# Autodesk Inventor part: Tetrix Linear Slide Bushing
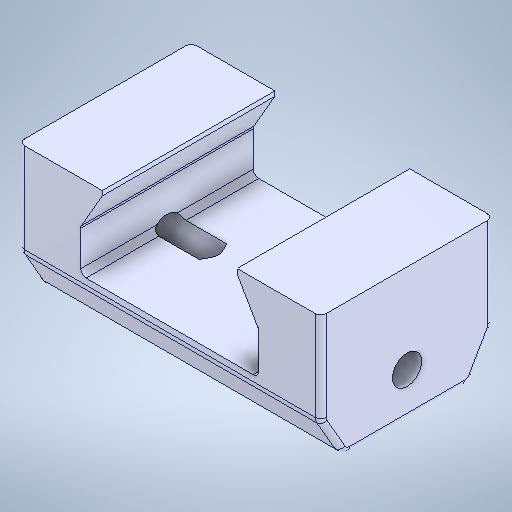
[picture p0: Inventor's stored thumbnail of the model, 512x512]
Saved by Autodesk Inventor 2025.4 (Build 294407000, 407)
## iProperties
Created: 2021-10
Part Number: Tetrix Linear Slide Bushing
Material: Genérico
Document SubType Name: Modeling
Designer: usuario
Density: 1 g/cm^3
Appearance: Valor por defecto
Author: usuario
Sending System: SolidWorks 2016
Last Author: LENOVO
Last Saved: 2021-10-23
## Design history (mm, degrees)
feature "M2.5 Clearance Hole2"
node "Sólido1"
